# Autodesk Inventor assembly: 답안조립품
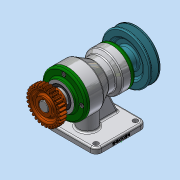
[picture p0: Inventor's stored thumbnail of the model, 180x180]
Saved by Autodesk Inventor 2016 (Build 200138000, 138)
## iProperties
Created: 2019-01
Part Number: 답안조립품
Document SubType Name: Assembly
Designer: MIRAE
Author: MIRAE
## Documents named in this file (15)
- C:\Users\MIRAE\Desktop\490108V1007\답안조립품.iam
- C:\Users\MIRAE\Desktop\490108V1007\본체.ipt
- C:\Users\MIRAE\Desktop\490108V1007\축.ipt
- C:\Users\MIRAE\Desktop\490108V1007\키 5 x 5 x 20.ipt
- C:\Users\MIRAE\Desktop\490108V1007\베어링 6203.ipt
- C:\Users\MIRAE\Desktop\490108V1007\뒤커버.ipt
- C:\Users\MIRAE\Desktop\490108V1007\V-벨트풀리.ipt
- C:\Users\MIRAE\Desktop\490108V1007\멈춤나사 M3.ipt
- C:\Users\MIRAE\Desktop\490108V1007\오일 실 17 30 8.ipt
- C:\Users\MIRAE\Desktop\490108V1007\볼트 M4.ipt
- C:\Users\MIRAE\Desktop\490108V1007\베어링 6205.ipt
- C:\Users\MIRAE\Desktop\490108V1007\오일 실 25 38 8.ipt
- C:\Users\MIRAE\Desktop\490108V1007\앞커버.ipt
- C:\Users\MIRAE\Desktop\490108V1007\키 6 x 6 x 18.ipt
- C:\Users\MIRAE\Desktop\490108V1007\스퍼기어.ipt
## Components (1 placed, 1 different names)
1. V-벨트풀리:1
